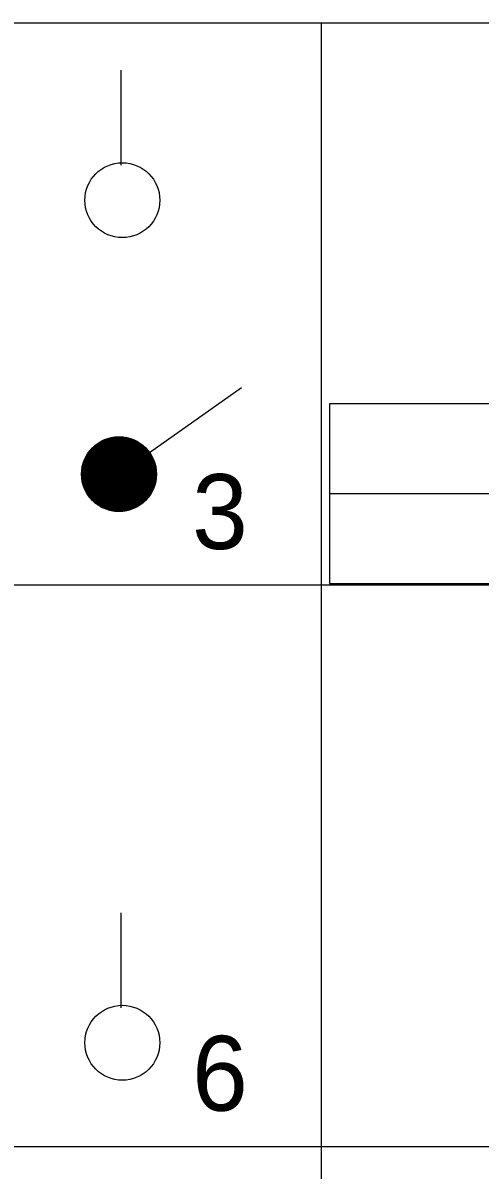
# Model space of a CAD drawing. Extents: x -28 to 822, y 61 to 665.
# Drawn here: x 265.16 to 277.36, y 351.11 to 381.74 of the extents above; entities that cross this region are included whole.
import ezdxf

# ---------------------------------------------------------------- set-up
doc = ezdxf.new("R2010")
doc.units = 0
doc.layers.add('KOLEJIŠTĚ', color=7, linetype='Continuous')

# ---------------------------------------------------------------- blocks, each defined once
blk = doc.blocks.new('ZT18')
for p, q in [((10, 6), (0, 6)), ((0, 6), (0, 2)), ((10, 2), (10, 6)), ((0, 2), (10, 2))]:
    blk.add_line(p, q)
blk.add_lwpolyline([(0, 4), (0, 4), (10, 4)])
blk = doc.blocks.new('_X10')
for p, q in [((370.452, 480.16), (371.464, 481.172)), ((370.452, 480.177), (371.447, 481.172)), ((370.452, 480.195), (371.429, 481.172)), ((370.453, 480.142), (371.482, 481.172)), ((370.453, 480.125), (371.499, 481.171)), ((370.453, 480.214), (371.411, 481.171)), ((370.454, 480.109), (371.515, 481.17)), ((370.454, 480.232), (371.392, 481.17)), ((370.455, 480.092), (371.532, 481.169)), ((370.455, 480.251), (371.373, 481.169)), ((370.457, 480.076), (371.548, 481.167)), ((370.457, 480.271), (371.353, 481.167)), ((370.458, 480.06), (371.564, 481.166)), ((370.459, 480.291), (371.334, 481.165)), ((370.46, 480.044), (371.58, 481.164)), ((370.462, 480.029), (371.596, 481.162)), ((370.462, 480.311), (371.313, 481.162)), ((370.465, 480.013), (371.611, 481.159)), ((370.465, 480.332), (371.293, 481.159)), ((370.467, 479.998), (371.626, 481.157)), ((370.469, 480.353), (371.271, 481.156)), ((370.47, 479.983), (371.641, 481.154)), ((370.473, 479.969), (371.656, 481.151)), ((370.473, 480.375), (371.249, 481.151)), ((370.476, 479.954), (371.67, 481.148)), ((370.478, 480.398), (371.227, 481.146)), ((370.479, 479.94), (371.685, 481.145)), ((370.483, 479.925), (371.699, 481.141)), ((370.484, 480.421), (371.203, 481.141)), ((370.487, 479.911), (371.713, 481.137)), ((370.49, 480.445), (371.179, 481.134)), ((370.491, 479.898), (371.727, 481.134)), ((370.495, 479.884), (371.74, 481.13)), ((370.498, 480.47), (371.154, 481.126)), ((370.499, 479.87), (371.754, 481.125)), ((370.503, 479.857), (371.767, 481.121)), ((370.506, 480.497), (371.127, 481.118)), ((370.507, 479.844), (371.78, 481.117)), ((370.512, 479.831), (371.793, 481.112)), ((370.516, 480.524), (371.1, 481.108)), ((370.517, 479.818), (371.806, 481.107)), ((370.522, 479.805), (371.819, 481.102)), ((370.527, 479.793), (371.832, 481.097)), ((370.528, 480.554), (371.071, 481.096)), ((370.532, 479.78), (371.844, 481.092)), ((370.537, 479.768), (371.856, 481.087)), ((370.541, 480.585), (371.039, 481.083)), ((370.543, 479.756), (371.869, 481.081)), ((370.549, 479.744), (371.881, 481.076)), ((370.554, 479.732), (371.893, 481.07)), ((370.557, 480.618), (371.006, 481.067)), ((370.56, 479.72), (371.904, 481.064)), ((370.566, 479.708), (371.916, 481.058)), ((370.572, 479.697), (371.928, 481.052)), ((370.577, 480.656), (370.968, 481.047)), ((370.579, 479.685), (371.939, 481.046)), ((370.585, 479.674), (371.95, 481.039)), ((370.592, 479.663), (371.961, 481.033)), ((370.598, 479.652), (371.972, 481.026)), ((370.602, 480.698), (370.926, 481.022)), ((370.605, 479.641), (371.983, 481.019)), ((370.612, 479.63), (371.994, 481.012)), ((370.619, 479.619), (372.005, 481.005)), ((370.626, 479.609), (372.015, 480.998)), ((370.633, 479.598), (372.026, 480.991)), ((370.637, 480.751), (370.873, 480.988)), ((370.64, 479.588), (372.036, 480.984)), ((370.648, 479.578), (372.046, 480.976)), ((370.655, 479.568), (372.057, 480.969)), ((370.663, 479.558), (372.067, 480.961)), ((370.671, 479.548), (372.076, 480.953)), ((370.679, 479.538), (372.086, 480.945)), ((370.687, 479.528), (372.096, 480.937)), ((370.695, 479.519), (372.105, 480.929)), ((370.703, 479.509), (372.115, 480.921)), ((370.706, 480.838), (370.786, 480.918)), ((370.712, 479.5), (372.124, 480.913)), ((370.72, 479.491), (372.133, 480.904)), ((370.729, 479.482), (372.142, 480.896)), ((370.737, 479.473), (372.151, 480.887)), ((370.746, 479.464), (372.16, 480.878)), ((370.755, 479.455), (372.169, 480.869)), ((370.764, 479.446), (372.178, 480.86)), ((370.773, 479.438), (372.186, 480.851)), ((370.782, 479.429), (372.195, 480.842)), ((370.792, 479.421), (372.203, 480.832)), ((370.801, 479.413), (372.211, 480.823)), ((370.811, 479.405), (372.219, 480.813)), ((370.821, 479.397), (372.227, 480.804)), ((370.83, 479.389), (372.235, 480.794)), ((370.84, 479.381), (372.243, 480.784)), ((370.85, 479.373), (372.251, 480.774)), ((370.86, 479.366), (372.258, 480.764)), ((370.871, 479.358), (372.266, 480.754)), ((370.881, 479.351), (372.273, 480.743)), ((370.891, 479.344), (372.28, 480.733)), ((370.902, 479.337), (372.287, 480.722)), ((370.913, 479.33), (372.294, 480.711)), ((370.924, 479.323), (372.301, 480.701)), ((370.935, 479.316), (372.308, 480.69)), ((370.946, 479.31), (372.314, 480.678)), ((370.957, 479.303), (372.321, 480.667)), ((370.968, 479.297), (372.327, 480.656)), ((370.98, 479.291), (372.333, 480.645)), ((370.991, 479.285), (372.34, 480.633)), ((371.003, 479.279), (372.346, 480.621)), ((371.015, 479.273), (372.351, 480.609)), ((371.027, 479.267), (372.357, 480.597)), ((371.039, 479.261), (372.363, 480.585)), ((371.051, 479.256), (372.368, 480.573)), ((371.063, 479.251), (372.373, 480.561)), ((371.076, 479.246), (372.379, 480.548)), ((371.089, 479.24), (372.384, 480.536)), ((371.101, 479.236), (372.389, 480.523)), ((371.114, 479.231), (372.393, 480.51)), ((371.127, 479.226), (372.398, 480.497)), ((371.141, 479.222), (372.402, 480.484)), ((371.154, 479.218), (372.407, 480.47)), ((371.167, 479.213), (372.411, 480.457)), ((371.181, 479.209), (372.415, 480.443)), ((371.195, 479.206), (372.419, 480.429)), ((371.209, 479.202), (372.422, 480.415)), ((371.223, 479.199), (372.426, 480.401)), ((371.238, 479.195), (372.429, 480.386)), ((371.252, 479.192), (372.432, 480.372)), ((371.267, 479.189), (372.435, 480.357)), ((371.282, 479.187), (372.438, 480.342)), ((371.297, 479.184), (372.44, 480.327)), ((371.313, 479.182), (372.442, 480.311)), ((371.328, 479.18), (372.444, 480.296)), ((371.344, 479.178), (372.446, 480.28)), ((371.36, 479.176), (372.448, 480.264)), ((371.376, 479.175), (372.449, 480.248)), ((371.393, 479.174), (372.45, 480.231)), ((371.41, 479.173), (372.451, 480.214)), ((371.427, 479.172), (372.452, 480.197)), ((371.444, 479.172), (372.452, 480.18)), ((371.462, 479.172), (372.452, 480.162)), ((371.48, 479.172), (372.452, 480.144)), ((371.498, 479.173), (372.451, 480.126)), ((371.517, 479.174), (372.45, 480.107)), ((371.536, 479.176), (372.449, 480.088)), ((371.556, 479.177), (372.447, 480.068)), ((371.576, 479.18), (372.444, 480.048)), ((371.596, 479.182), (372.442, 480.028)), ((371.617, 479.186), (372.438, 480.007)), ((371.639, 479.19), (372.435, 479.985)), ((371.661, 479.194), (372.43, 479.963)), ((371.684, 479.199), (372.425, 479.941)), ((371.707, 479.205), (372.419, 479.917)), ((371.732, 479.212), (372.412, 479.892)), ((371.757, 479.22), (372.404, 479.867)), ((371.784, 479.229), (372.395, 479.84)), ((371.812, 479.239), (372.385, 479.812)), ((371.841, 479.251), (372.373, 479.783)), ((371.873, 479.265), (372.359, 479.751)), ((371.908, 479.282), (372.342, 479.716)), ((371.946, 479.303), (372.322, 479.678)), ((371.991, 479.329), (372.295, 479.634)), ((372.047, 479.369), (372.256, 479.577))]:
    blk.add_line(p, q)

msp = doc.modelspace()

# ---------------------------------------------------------------- linework, layer by layer
for p, q in [((5.068, 381.738), (540.616, 381.738)), ((5.068, 381.738), (293.116, 381.738)), ((5.068, 381.738), (293.116, 381.738)), ((273.116, 381.738), (273.116, 111.738)), ((273.116, 381.738), (273.116, 336.738)), ((273.116, 381.738), (273.116, 111.738)), ((267.778, 377.941), (267.778, 380.474)), ((268.536, 370.267), (270.986, 371.999)), ((5.068, 366.738), (292.72, 366.738)), ((267.778, 355.441), (267.778, 357.974)), ((5.068, 351.738), (540.616, 351.738))]:
    msp.add_line(p, q)
for centre in [(267.81, 377.005), (267.72, 369.689), (267.81, 354.505)]:
    msp.add_circle(centre, 1)

# ---------------------------------------------------------------- block references
at = {"rotation": -92.29148628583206}
msp.add_blockref('_X10', (-197.216, 760.043), dxfattribs=at)
at = {"layer": 'KOLEJIŠTĚ', "xscale": 1.2000000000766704, "yscale": 1.2000000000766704}
msp.add_blockref('ZT18', (273.343, 364.37), dxfattribs=at)

# ---------------------------------------------------------------- texts
for s, p in [('3', (269.672, 367.69)), ('6', (269.672, 352.69))]:
    msp.add_text(s, height=2).set_placement(p)

doc.saveas('drawing.dxf')
